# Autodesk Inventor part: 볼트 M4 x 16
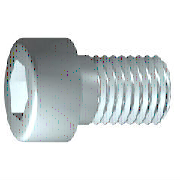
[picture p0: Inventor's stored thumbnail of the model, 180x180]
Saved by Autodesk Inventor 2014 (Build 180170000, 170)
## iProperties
IsCustomPart: 1
Created: 2012-02
Part Number: 볼트 M4 x 16
Material: 스테인리스강
Description: 6각 소켓 머리 캡 나사
Document SubType Name: Modeling
Standard: ISO 4762
Designer: mduedu
Standard Revision: Fourth edition 2004-03-01
Standards Organization: ISO
Language: ko-KR
Size Designation: M4 x 16
Categories: <MemberInstance><Categories><Category DisplayName="조임쇠" InternalName="e4da775c-781d-43d5-af7c-5136215cf5a6" Mnemonic="FSTN"><Category DisplayName="볼트" InternalN
Density: 8.08 g/cm^3
Appearance: 반광택
Mass: 2.70334 g
Surface Area: 3.81118 cm^2
Volume: 0.334572 cm^3
Author: mduedu
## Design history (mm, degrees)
sketch "스케치1"
  geometry: L1 (-1, 0)-(16, 0); L2 (16, 0)-(16, 2); L3 (16, 2)-(1.75, 2); L4 (1.75, 2)-(1.32, 2); L5 (1.32, 2)-(0, 2); L6 (0, 2)-(0, 3.5); L7 (0, 3.5)-(-4, 3.5); L8 (-4, 3.5)-(-4, 1.732); L9 (-4, 1.732)-(-2, 1.732); L10 (-2, 1.732)-(-1, 0); L11 (-8, 0)-(20, 0) reference; L12 (0, -0.7)-(0, 4.2) reference; L13 (1.75, 2)-(0, 2)
  constraints: 22 end point, 6 parallel, 2 collinear, 2 perpendicular, 1 horizontal, 1 point on line
  dimensions: "d1" = 14.25 distance from line of L3.end L2 (= GEL); "d2" = 0.42952 distance of L4.end L3.end (computed from GAL); "d3" = 4 distance between parallel lines of L8 L6 (= KOH); "d4" = 2 distance of L8.end L9.end (= INTI); "d5" = 60 deg angle of L10 L1; "d6" = 4 diameter of L3 L1 (= GD); "d7" = 4 diameter of L5 L1 (= BDM); "d8" = 3.4641 diameter of L9 L1 (= 1.1547 x SW); "d9" = 7 diameter of L7 L1 (= KOD); "d26" = 16 distance between parallel lines of L12 L2 (= NLG)
revolve "본체" sketch "스케치1" stored, may be unused: angle "d10" = 90 deg
sketch "스케치2"
  geometry: L1 (0, -4.9)-(0, 4.9) reference; L2 (-4.9, 0)-(4.9, 0) reference; L3 (1.732, 0)-(0.866, -1.5); L4 (0.866, -1.5)-(-0.866, -1.5); L5 (-0.866, -1.5)-(-1.732, 0); L6 (-1.732, 0)-(-0.866, 1.5); L7 (-0.866, 1.5)-(0.866, 1.5); L8 (0.866, 1.5)-(1.732, 0); 2 further points
  constraints: 12 end point, 1 coincident, 1 horizontal alignment, 1 point on line, 12 other
extrude "슬롯" join sketch "스케치2" stored distance "d11" = 10; taper "d12" = 0 deg
workplane "Work Plane1"
fillet "Fillet2" dims "d30" = 0.1 (= R)
body "Solid1"
fillet "모깎기1" dims "d17" = 0.4 (= RR)
feature "스레드" dims "d13" = 14.25 (= GEL), "d14" = 0
chamfer "모따기1" distance "d15" = 0.42941 (= -0.5 x SPD + 0.5 x GD); stored, may be unused: second distance "d16" = 0.42941 (= GUL), angle "d27" = 45 deg
other parameters: "GD" = 4 [user parameter; used in 2 equation terms], "NLG" = 16 [user parameter; used in 1 equation term], "GEL" = 14.25 [user parameter; used in 2 equation terms], "KOD" = 7 [user parameter; used in 1 equation term], "KOH" = 4 [user parameter; used in 1 equation term], "INTI" = 2 [user parameter; used in 1 equation term], "GAL" = 0.42941 (= 0.61345 x PTC) [user parameter; used in 1 equation term], "GUL" = 0.42941 (= 0.61345 x PTC) [user parameter; used in 1 equation term], "BDM" = 4 (= NND) [user parameter; used in 1 equation term], "SW" = 3 [user parameter; used in 2 equation terms], "RR" = 0.4 [user parameter; used in 1 equation term], "SPD" = 3.14117 (= NND - 1.2269 x PTC) [user parameter; used in 1 equation term], "d19" = 0, "d28" = 0, "d29" = 0, "R" = 0.1 [user parameter; used in 1 equation term], "TOA" = 30 deg [user parameter], "GD1" = 3.14117 (= THREADDIA - 1.2269 x PTC) [user parameter], "THREADDIA" = 4 [user parameter; used in 1 equation term], "FAWI" = 45 deg [user parameter], "TPU" = 14.28571 (computed from PTC) [user parameter], "PTC" = 0.7 [user parameter; used in 5 equation terms], "NND" = 4 [user parameter; used in 2 equation terms], "E0" = 3.465 (= 1.155 x SW) [user parameter]
